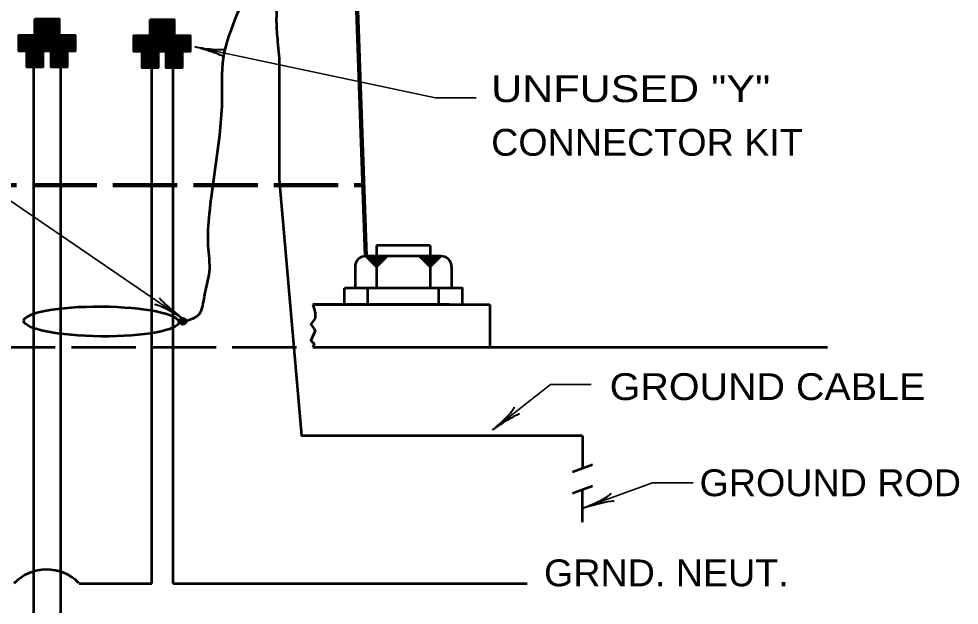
# Model space of a CAD drawing. Extents: x -153 to 527, y -247 to 194.
# Drawn here: x 102.3 to 190, y -178.9 to -124.2 of the extents above; entities that cross this region are included whole.
import ezdxf

# ---------------------------------------------------------------- set-up
doc = ezdxf.new("R2010")
doc.units = 0
doc.linetypes.add('LONG_DASHED', pattern=[7.5, 6, -1.5])
doc.layers.add('1', color=7, linetype='Continuous', lineweight=53)

msp = doc.modelspace()

# ---------------------------------------------------------------- linework, layer by layer
at = {"layer": '1', "lineweight": 90}
msp.add_line((134.641, -146.336), (131.815, -65.386), dxfattribs=at)
at = {"layer": '1'}
for p, q in [((103.79, -124.381), (106.04, -124.381)), ((114.525, -124.432), (116.775, -124.432)), ((103.79, -124.531), (106.04, -124.531)), ((103.79, -124.707), (106.04, -124.707)), ((103.79, -124.857), (106.04, -124.857)), ((103.79, -125.008), (106.04, -125.008)), ((103.79, -125.183), (106.04, -125.183)), ((103.79, -125.334), (106.04, -125.334)), ((114.525, -124.582), (116.775, -124.582)), ((114.525, -124.758), (116.775, -124.758)), ((114.525, -124.908), (116.775, -124.908)), ((114.525, -125.059), (116.775, -125.059)), ((114.525, -125.234), (116.775, -125.234)), ((102.29, -125.835), (103.79, -125.835)), ((102.29, -125.935), (103.79, -125.935)), ((102.29, -126.061), (103.79, -126.061)), ((102.29, -126.211), (103.79, -126.211)), ((103.79, -125.509), (106.04, -125.509)), ((103.79, -125.685), (106.04, -125.685)), ((103.79, -125.835), (106.04, -125.835)), ((103.79, -126.011), (106.04, -126.011)), ((103.79, -126.136), (106.04, -126.136)), ((103.79, -126.236), (106.04, -126.236)), ((106.04, -125.785), (107.54, -125.785)), ((106.04, -125.91), (107.54, -125.91)), ((106.04, -126.011), (107.54, -126.011)), ((106.04, -126.161), (107.54, -126.161)), ((113.025, -125.886), (114.525, -125.886)), ((113.025, -125.986), (114.525, -125.986)), ((113.025, -126.112), (114.525, -126.112)), ((114.525, -125.385), (116.775, -125.385)), ((114.525, -125.56), (116.775, -125.56)), ((114.525, -125.736), (116.775, -125.736)), ((114.525, -125.886), (116.775, -125.886)), ((114.525, -126.061), (116.775, -126.061)), ((114.525, -126.187), (116.775, -126.187)), ((116.775, -125.836), (118.275, -125.836)), ((116.775, -125.961), (118.275, -125.961)), ((116.775, -126.061), (118.275, -126.061)), ((116.775, -126.212), (118.275, -126.212)), ((102.29, -126.337), (103.79, -126.337)), ((102.29, -126.512), (103.79, -126.512)), ((102.29, -126.688), (103.79, -126.688)), ((102.29, -126.788), (103.79, -126.788)), ((102.29, -126.913), (103.79, -126.913)), ((102.29, -127.014), (103.79, -127.014)), ((103.79, -126.312), (106.04, -126.312)), ((103.79, -126.362), (106.04, -126.362)), ((103.79, -126.437), (106.04, -126.437)), ((103.79, -126.587), (106.04, -126.587)), ((103.79, -126.663), (106.04, -126.663)), ((103.79, -126.838), (106.04, -126.838)), ((103.79, -126.989), (106.04, -126.989)), ((103.79, -127.114), (106.04, -127.114)), ((106.04, -126.337), (107.54, -126.337)), ((106.04, -126.462), (107.54, -126.462)), ((106.04, -126.612), (107.54, -126.612)), ((106.04, -126.738), (107.54, -126.738)), ((106.04, -126.863), (107.54, -126.863)), ((106.04, -126.989), (107.54, -126.989)), ((113.025, -126.262), (114.525, -126.262)), ((113.025, -126.387), (114.525, -126.387)), ((113.025, -126.563), (114.525, -126.563)), ((113.025, -126.738), (114.525, -126.738)), ((113.025, -126.839), (114.525, -126.839)), ((113.025, -126.964), (114.525, -126.964)), ((113.025, -127.064), (114.525, -127.064)), ((114.525, -126.287), (116.775, -126.287)), ((114.525, -126.362), (116.775, -126.362)), ((114.525, -126.412), (116.775, -126.412)), ((114.525, -126.488), (116.775, -126.488)), ((114.525, -126.638), (116.775, -126.638)), ((114.525, -126.713), (116.775, -126.713)), ((114.525, -126.889), (116.775, -126.889)), ((114.525, -127.039), (116.775, -127.039)), ((116.775, -126.387), (118.275, -126.387)), ((116.775, -126.513), (118.275, -126.513)), ((116.775, -126.663), (118.275, -126.663)), ((116.775, -126.789), (118.275, -126.789)), ((116.775, -126.914), (118.275, -126.914)), ((116.775, -127.039), (118.275, -127.039)), ((102.29, -127.164), (103.79, -127.164)), ((104.54, -127.239), (103.04, -127.239)), ((104.54, -127.264), (103.04, -127.264)), ((104.54, -127.34), (103.04, -127.34)), ((104.54, -127.44), (103.04, -127.44)), ((104.54, -127.54), (103.04, -127.54)), ((104.54, -127.615), (103.04, -127.615)), ((104.54, -127.665), (103.04, -127.665)), ((104.54, -127.716), (103.04, -127.716)), ((104.54, -127.816), (103.04, -127.816)), ((104.54, -127.891), (103.04, -127.891)), ((104.54, -127.991), (103.04, -127.991)), ((106.79, -127.189), (105.29, -127.189)), ((106.79, -127.239), (105.29, -127.239)), ((106.79, -127.289), (105.29, -127.289)), ((106.79, -127.34), (105.29, -127.34)), ((106.79, -127.415), (105.29, -127.415)), ((106.79, -127.49), (105.29, -127.49)), ((106.79, -127.54), (105.29, -127.54)), ((106.79, -127.59), (105.29, -127.59)), ((106.79, -127.665), (105.29, -127.665)), ((106.79, -127.716), (105.29, -127.716)), ((106.79, -127.791), (105.29, -127.791)), ((106.79, -127.841), (105.29, -127.841)), ((106.79, -127.866), (105.29, -127.866)), ((106.79, -127.916), (105.29, -127.916)), ((106.79, -127.941), (105.29, -127.941)), ((106.79, -127.991), (105.29, -127.991)), ((106.04, -127.139), (107.54, -127.139)), ((113.025, -127.215), (114.525, -127.215)), ((115.275, -127.29), (113.775, -127.29)), ((115.275, -127.315), (113.775, -127.315)), ((115.275, -127.39), (113.775, -127.39)), ((115.275, -127.491), (113.775, -127.491)), ((115.275, -127.591), (113.775, -127.591)), ((115.275, -127.666), (113.775, -127.666)), ((115.275, -127.716), (113.775, -127.716)), ((115.275, -127.766), (113.775, -127.766)), ((115.275, -127.867), (113.775, -127.867)), ((115.275, -127.942), (113.775, -127.942)), ((114.525, -127.165), (116.775, -127.165)), ((117.525, -127.24), (116.025, -127.24)), ((117.525, -127.29), (116.025, -127.29)), ((117.525, -127.34), (116.025, -127.34)), ((117.525, -127.39), (116.025, -127.39)), ((117.525, -127.465), (116.025, -127.465)), ((117.525, -127.541), (116.025, -127.541)), ((117.525, -127.591), (116.025, -127.591)), ((117.525, -127.641), (116.025, -127.641)), ((117.525, -127.716), (116.025, -127.716)), ((117.525, -127.766), (116.025, -127.766)), ((117.525, -127.842), (116.025, -127.842)), ((117.525, -127.892), (116.025, -127.892)), ((117.525, -127.917), (116.025, -127.917)), ((117.525, -127.967), (116.025, -127.967)), ((117.525, -127.992), (116.025, -127.992)), ((116.775, -127.19), (118.275, -127.19)), ((104.54, -128.092), (103.04, -128.092)), ((104.54, -128.217), (103.04, -128.217)), ((104.54, -128.317), (103.04, -128.317)), ((104.54, -128.418), (103.04, -128.418)), ((104.54, -128.518), (103.04, -128.518)), ((104.54, -128.618), (103.04, -128.618)), ((103.692, -181.835), (103.692, -128.731)), ((106.79, -128.042), (105.29, -128.042)), ((106.79, -128.092), (105.29, -128.092)), ((106.79, -128.167), (105.29, -128.167)), ((106.79, -128.242), (105.29, -128.242)), ((106.79, -128.317), (105.29, -128.317)), ((106.79, -128.368), (105.29, -128.368)), ((106.79, -128.418), (105.29, -128.418)), ((106.79, -128.468), (105.29, -128.468)), ((106.79, -128.543), (105.29, -128.543)), ((106.79, -128.568), (105.29, -128.568)), ((106.192, -181.835), (106.192, -128.731)), ((115.275, -128.042), (113.775, -128.042)), ((115.275, -128.142), (113.775, -128.142)), ((115.275, -128.268), (113.775, -128.268)), ((115.275, -128.368), (113.775, -128.368)), ((115.275, -128.468), (113.775, -128.468)), ((115.275, -128.569), (113.775, -128.569)), ((115.275, -128.669), (113.775, -128.669)), ((114.692, -176.836), (114.692, -128.781)), ((117.525, -128.042), (116.025, -128.042)), ((117.525, -128.092), (116.025, -128.092)), ((117.525, -128.142), (116.025, -128.142)), ((117.525, -128.218), (116.025, -128.218)), ((117.525, -128.293), (116.025, -128.293)), ((117.525, -128.368), (116.025, -128.368)), ((117.525, -128.418), (116.025, -128.418)), ((117.525, -128.468), (116.025, -128.468)), ((117.525, -128.519), (116.025, -128.519)), ((117.525, -128.594), (116.025, -128.594)), ((117.525, -128.619), (116.025, -128.619)), ((116.692, -176.836), (116.692, -128.781)), ((135.641, -145.336), (135.641, -149.336)), ((140.641, -145.336), (135.641, -145.336)), ((140.641, -145.336), (140.641, -149.336)), ((135.635, -147.34), (134.635, -146.34)), ((141.641, -146.336), (134.641, -146.336)), ((135.641, -147.336), (134.641, -146.336)), ((135.649, -147.325), (134.664, -146.34)), ((135.662, -147.312), (134.686, -146.336)), ((135.662, -147.312), (134.689, -146.34)), ((135.674, -147.3), (134.714, -146.34)), ((135.687, -147.287), (134.739, -146.34)), ((135.693, -147.281), (134.752, -146.34)), ((135.696, -147.278), (134.754, -146.336)), ((135.707, -147.267), (134.776, -146.336)), ((135.709, -147.265), (134.783, -146.34)), ((135.71, -147.264), (134.786, -146.34)), ((135.721, -147.253), (134.808, -146.34)), ((135.688, -147.286), (134.816, -146.414)), ((135.726, -147.248), (134.817, -146.34)), ((135.704, -147.27), (134.832, -146.398)), ((135.709, -147.266), (134.836, -146.393)), ((135.71, -147.264), (134.838, -146.392)), ((135.71, -147.264), (134.838, -146.392)), ((135.737, -147.237), (134.84, -146.34)), ((135.718, -147.256), (134.846, -146.384)), ((135.723, -147.251), (134.85, -146.379)), ((135.745, -147.229), (134.855, -146.34)), ((135.727, -147.247), (134.855, -146.374)), ((135.746, -147.228), (134.858, -146.34)), ((135.748, -147.226), (134.875, -146.354)), ((135.757, -147.217), (134.885, -146.345)), ((135.76, -147.214), (134.888, -146.341)), ((135.762, -147.212), (134.89, -146.34)), ((135.77, -147.204), (134.902, -146.336)), ((135.773, -147.201), (134.911, -146.34)), ((135.782, -147.192), (134.93, -146.34)), ((135.793, -147.181), (134.949, -146.336)), ((135.795, -147.179), (134.955, -146.34)), ((135.798, -147.176), (134.962, -146.34)), ((135.803, -147.171), (134.971, -146.34)), ((135.81, -147.164), (134.983, -146.336)), ((135.812, -147.162), (134.99, -146.34)), ((135.823, -147.151), (135.008, -146.336)), ((135.825, -147.149), (135.015, -146.34)), ((135.829, -147.145), (135.021, -146.336)), ((135.828, -147.146), (135.021, -146.34)), ((135.839, -147.135), (135.043, -146.34)), ((135.848, -147.126), (135.059, -146.336)), ((135.854, -147.12), (135.071, -146.336)), ((135.859, -147.115), (135.081, -146.336)), ((135.864, -147.11), (135.09, -146.336)), ((135.862, -147.112), (135.09, -146.34)), ((135.868, -147.106), (135.096, -146.334)), ((135.867, -147.107), (135.1, -146.34)), ((135.878, -147.096), (135.118, -146.336)), ((135.878, -147.096), (135.118, -146.336)), ((135.876, -147.098), (135.118, -146.34)), ((135.884, -147.09), (135.131, -146.336)), ((135.891, -147.084), (135.143, -146.336)), ((135.9, -147.074), (135.162, -146.336)), ((135.901, -147.073), (135.165, -146.336)), ((135.906, -147.068), (135.174, -146.336)), ((135.912, -147.062), (135.19, -146.34)), ((135.917, -147.057), (135.196, -146.336)), ((135.925, -147.049), (135.216, -146.34)), ((135.93, -147.045), (135.221, -146.336)), ((135.936, -147.038), (135.237, -146.34)), ((135.925, -147.049), (135.275, -146.399)), ((135.963, -147.011), (135.291, -146.34)), ((135.942, -147.032), (135.292, -146.382)), ((135.964, -147.01), (135.314, -146.36)), ((135.974, -147.001), (135.324, -146.351)), ((135.978, -146.996), (135.328, -146.346)), ((135.985, -146.989), (135.335, -146.34)), ((135.992, -146.982), (135.347, -146.336)), ((135.994, -146.98), (135.353, -146.34)), ((136, -146.974), (135.366, -146.34)), ((136.008, -146.966), (135.378, -146.336)), ((136.008, -146.966), (135.378, -146.336)), ((136.016, -146.958), (135.394, -146.336)), ((136.024, -146.951), (135.41, -146.336)), ((136.025, -146.949), (135.413, -146.336)), ((136.027, -146.947), (135.419, -146.34)), ((136.03, -146.944), (135.422, -146.336)), ((136.03, -146.944), (135.422, -146.337)), ((136.036, -146.938), (135.435, -146.336)), ((136.035, -146.939), (135.435, -146.34)), ((136.041, -146.933), (135.444, -146.336)), ((136.05, -146.924), (135.463, -146.336)), ((136.051, -146.924), (135.467, -146.34)), ((136.058, -146.916), (135.479, -146.336)), ((136.066, -146.908), (135.498, -146.34)), ((136.093, -146.881), (135.551, -146.34)), ((136.102, -146.872), (135.566, -146.336)), ((136.112, -146.863), (135.585, -146.336)), ((136.113, -146.861), (135.588, -146.336)), ((135.635, -147.34), (136.635, -146.34)), ((135.641, -147.336), (136.641, -146.336)), ((136.138, -146.836), (135.642, -146.34)), ((136.138, -146.836), (135.642, -146.34)), ((136.149, -146.825), (135.661, -146.336)), ((136.151, -146.823), (135.672, -146.344)), ((136.155, -146.819), (135.676, -146.34)), ((136.159, -146.816), (135.679, -146.337)), ((136.162, -146.812), (135.685, -146.336)), ((136.165, -146.809), (135.692, -146.336)), ((136.171, -146.803), (135.704, -146.336)), ((136.179, -146.795), (135.72, -146.336)), ((136.185, -146.789), (135.736, -146.34)), ((136.191, -146.783), (135.745, -146.336)), ((136.198, -146.776), (135.761, -146.34)), ((136.202, -146.772), (135.767, -146.336)), ((136.214, -146.761), (135.793, -146.34)), ((136.224, -146.75), (135.814, -146.34)), ((136.227, -146.747), (135.817, -146.336)), ((136.235, -146.739), (135.833, -146.336)), ((136.251, -146.723), (135.868, -146.34)), ((136.27, -146.704), (135.902, -146.336)), ((136.268, -146.706), (135.902, -146.34)), ((136.273, -146.701), (135.911, -146.34)), ((136.276, -146.698), (135.915, -146.336)), ((136.282, -146.692), (135.927, -146.336)), ((136.285, -146.689), (135.933, -146.336)), ((136.293, -146.681), (135.949, -146.336)), ((136.308, -146.667), (135.977, -146.336)), ((136.315, -146.659), (135.993, -146.336)), ((136.326, -146.648), (136.015, -146.336)), ((136.345, -146.629), (136.053, -146.336)), ((136.351, -146.623), (136.065, -146.336)), ((136.356, -146.618), (136.077, -146.34)), ((136.383, -146.591), (136.131, -146.34)), ((136.394, -146.58), (136.153, -146.34)), ((136.414, -146.56), (136.194, -146.34)), ((136.427, -146.547), (136.219, -146.34)), ((136.434, -146.54), (136.23, -146.336)), ((136.439, -146.535), (136.24, -146.336)), ((136.442, -146.532), (136.247, -146.336)), ((136.477, -146.497), (136.319, -146.34)), ((136.483, -146.491), (136.328, -146.336)), ((136.503, -146.471), (136.369, -146.336)), ((136.48, -146.495), (136.397, -146.412)), ((136.514, -146.46), (136.431, -146.378)), ((136.519, -146.456), (136.436, -146.373)), ((136.54, -146.435), (136.441, -146.336)), ((136.529, -146.446), (136.446, -146.363)), ((136.532, -146.442), (136.449, -146.36)), ((136.552, -146.422), (136.469, -146.34)), ((136.555, -146.419), (136.473, -146.337)), ((136.56, -146.414), (136.482, -146.336)), ((136.569, -146.405), (136.501, -146.336)), ((136.623, -146.351), (136.607, -146.336)), ((140.641, -147.336), (139.641, -146.336)), ((140.656, -147.322), (139.671, -146.336)), ((140.669, -147.309), (139.696, -146.336)), ((140.669, -147.309), (139.696, -146.336)), ((140.681, -147.297), (139.721, -146.336)), ((140.694, -147.284), (139.746, -146.336)), ((140.7, -147.278), (139.758, -146.336)), ((140.716, -147.262), (139.79, -146.336)), ((140.717, -147.261), (139.793, -146.336)), ((140.728, -147.25), (139.815, -146.336)), ((140.733, -147.245), (139.824, -146.336)), ((140.744, -147.234), (139.846, -146.336)), ((140.744, -147.234), (139.847, -146.336)), ((140.752, -147.226), (139.862, -146.336)), ((140.753, -147.225), (139.865, -146.336)), ((140.763, -147.215), (139.884, -146.336)), ((140.766, -147.212), (139.89, -146.336)), ((140.769, -147.209), (139.897, -146.336)), ((140.789, -147.189), (139.937, -146.336)), ((140.802, -147.176), (139.962, -146.336)), ((140.81, -147.168), (139.978, -146.336)), ((140.819, -147.159), (139.997, -146.336)), ((140.832, -147.146), (140.022, -146.336)), ((140.846, -147.132), (140.05, -146.336)), ((140.853, -147.124), (140.065, -146.336)), ((140.86, -147.118), (140.078, -146.336)), ((140.869, -147.108), (140.097, -146.336)), ((140.874, -147.104), (140.106, -146.336)), ((140.883, -147.094), (140.125, -146.336)), ((140.89, -147.088), (140.138, -146.336)), ((140.9, -147.077), (140.16, -146.336)), ((140.919, -147.058), (140.197, -146.336)), ((140.929, -147.049), (140.216, -146.336)), ((140.932, -147.046), (140.222, -146.336)), ((140.932, -147.046), (140.223, -146.336)), ((140.943, -147.035), (140.244, -146.336)), ((140.951, -147.027), (140.26, -146.336)), ((140.965, -147.013), (140.288, -146.336)), ((140.97, -147.008), (140.298, -146.336)), ((140.982, -146.996), (140.323, -146.336)), ((140.992, -146.986), (140.342, -146.336)), ((141.001, -146.977), (140.36, -146.336)), ((141.007, -146.971), (140.373, -146.336)), ((141.009, -146.969), (140.376, -146.336)), ((141.034, -146.944), (140.426, -146.336)), ((141.042, -146.936), (140.442, -146.336)), ((141.048, -146.93), (140.454, -146.336)), ((141.054, -146.924), (140.467, -146.336)), ((141.054, -146.924), (140.467, -146.336)), ((141.057, -146.92), (140.473, -146.336)), ((141.057, -146.921), (140.473, -146.336)), ((141.062, -146.916), (140.482, -146.336)), ((141.073, -146.905), (140.505, -146.336)), ((141.1, -146.878), (140.558, -146.336)), ((141.111, -146.867), (140.58, -146.336)), ((141.118, -146.859), (140.595, -146.336)), ((140.641, -147.336), (141.641, -146.336)), ((141.145, -146.833), (140.649, -146.336)), ((141.145, -146.833), (140.649, -146.336)), ((141.15, -146.828), (140.658, -146.336)), ((141.156, -146.822), (140.671, -146.336)), ((141.159, -146.819), (140.677, -146.336)), ((141.162, -146.815), (140.683, -146.336)), ((141.165, -146.812), (140.689, -146.336)), ((141.192, -146.786), (140.743, -146.336)), ((141.205, -146.773), (140.768, -146.336)), ((141.211, -146.767), (140.78, -146.336)), ((141.214, -146.764), (140.787, -146.336)), ((141.22, -146.757), (140.799, -146.336)), ((141.225, -146.753), (140.809, -146.336)), ((141.231, -146.747), (140.821, -146.336)), ((141.236, -146.742), (140.831, -146.336)), ((141.258, -146.72), (140.875, -146.336)), ((141.275, -146.703), (140.909, -146.336)), ((141.28, -146.698), (140.918, -146.336)), ((141.285, -146.693), (140.928, -146.336)), ((141.314, -146.663), (140.987, -146.336)), ((141.322, -146.656), (141.003, -146.336)), ((141.333, -146.645), (141.025, -146.336)), ((141.335, -146.643), (141.028, -146.336)), ((141.352, -146.626), (141.062, -146.336)), ((141.363, -146.615), (141.084, -146.336)), ((141.39, -146.588), (141.138, -146.336)), ((141.421, -146.557), (141.201, -146.336)), ((141.426, -146.552), (141.21, -146.336)), ((141.434, -146.544), (141.226, -146.336)), ((141.438, -146.54), (141.235, -146.336)), ((141.46, -146.518), (141.279, -146.336)), ((141.484, -146.494), (141.326, -146.336)), ((141.486, -146.492), (141.404, -146.409)), ((141.521, -146.457), (141.438, -146.375)), ((141.525, -146.452), (141.443, -146.37)), ((141.529, -146.449), (141.446, -146.367)), ((141.546, -146.432), (141.463, -146.35)), ((141.559, -146.419), (141.476, -146.336)), ((141.601, -146.377), (141.56, -146.337)), ((141.608, -146.369), (141.575, -146.336)), ((141.615, -146.363), (141.589, -146.337)), ((141.621, -146.357), (141.604, -146.34)), ((135.873, -147.101), (135.223, -146.451)), ((135.9, -147.074), (135.25, -146.424)), ((135.908, -147.066), (135.258, -146.417)), ((135.762, -147.213), (135.679, -147.13)), ((135.798, -147.177), (135.716, -147.094)), ((136.044, -146.931), (135.962, -146.848)), ((136.268, -146.706), (135.979, -146.416)), ((136.108, -146.866), (136.026, -146.784)), ((136.162, -146.813), (136.079, -146.731)), ((136.179, -146.796), (136.096, -146.713)), ((136.221, -146.753), (136.138, -146.671)), ((136.284, -146.691), (136.201, -146.608)), ((136.357, -146.617), (136.275, -146.535)), ((136.469, -146.506), (136.386, -146.423)), ((140.739, -147.239), (140.657, -147.157)), ((140.805, -147.174), (140.722, -147.091)), ((140.875, -147.103), (140.793, -147.021)), ((140.965, -147.014), (140.882, -146.931)), ((141.051, -146.927), (140.968, -146.845)), ((141.063, -146.915), (140.981, -146.832)), ((141.084, -146.894), (141.001, -146.812)), ((141.087, -146.891), (141.005, -146.809)), ((141.115, -146.863), (141.033, -146.781)), ((141.118, -146.86), (141.036, -146.777)), ((141.145, -146.833), (141.062, -146.751)), ((141.153, -146.826), (141.07, -146.743)), ((141.168, -146.81), (141.086, -146.727)), ((141.186, -146.793), (141.103, -146.71)), ((141.228, -146.75), (141.145, -146.668)), ((141.291, -146.688), (141.208, -146.605)), ((141.342, -146.636), (141.26, -146.553)), ((141.392, -146.586), (141.31, -146.503)), ((141.424, -146.554), (141.341, -146.472)), ((141.461, -146.517), (141.379, -146.434)), ((141.475, -146.502), (141.393, -146.42)), ((133.641, -147.336), (133.641, -149.336)), ((142.641, -147.336), (142.641, -149.336)), ((132.641, -150.836), (132.641, -149.336)), ((134.839, -150.836), (134.839, -149.336)), ((141.451, -150.836), (141.451, -149.336)), ((129.692, -150.836), (146.192, -150.836)), ((142.4, -150.836), (129.692, -150.836)), ((146.192, -150.836), (146.192, -154.836)), ((129.692, -154.836), (177.692, -154.836)), ((154.841, -163.092), (154.841, -166.092)), ((153.902, -166.434), (155.781, -165.75)), ((153.902, -168.434), (155.781, -167.75)), ((154.826, -168.117), (154.826, -171.117)), ((107.915, -176.836), (114.692, -176.836)), ((116.692, -176.836), (149.692, -176.836))]:
    msp.add_line(p, q, dxfattribs=at)
at = {"layer": '1', "lineweight": 35}
for p, q in [((118.714, -126.824), (141.129, -131.588)), ((87.001, -131.25), (117.556, -152.159)), ((144.928, -131.588), (141.129, -131.588)), ((151.852, -158.315), (146.47, -162.52)), ((155.65, -158.315), (151.852, -158.315)), ((161.361, -167.474), (154.942, -169.81)), ((165.159, -167.474), (161.361, -167.474))]:
    msp.add_line(p, q, dxfattribs=at)
at = {"layer": '1', "linetype": 'LONG_DASHED', "lineweight": 90}
msp.add_line((88.564, -139.723), (134.41, -139.723), dxfattribs=at)
at = {"layer": '1', "linetype": 'LONG_DASHED'}
msp.add_line((92.192, -154.836), (129.692, -154.836), dxfattribs=at)
at = {"layer": '1'}
for points in [[(103.79, -124.231), (106.04, -124.231), (106.04, -125.731), (107.54, -125.731), (107.54, -127.231), (106.79, -127.231), (106.79, -128.731), (105.29, -128.731), (105.29, -127.231), (104.54, -127.231), (104.54, -128.731), (103.04, -128.731), (103.04, -127.231), (102.29, -127.231), (102.29, -125.731), (103.79, -125.731)], [(114.525, -124.281), (116.775, -124.281), (116.775, -125.781), (118.275, -125.781), (118.275, -127.281), (117.525, -127.281), (117.525, -128.781), (116.025, -128.781), (116.025, -127.281), (115.275, -127.281), (115.275, -128.781), (113.775, -128.781), (113.775, -127.281), (113.025, -127.281), (113.025, -125.781), (114.525, -125.781)]]:
    msp.add_lwpolyline(points, close=True, dxfattribs=at)
for points in [[(154.841, -163.092), (128.687, -163.092), (126.595, -139.184), (126.595, -130.184)], [(143.641, -150.836), (143.641, -149.336), (132.641, -149.336)], [(129.692, -150.836), (129.91, -151.606), (129.91, -152.108), (129.509, -152.71), (129.81, -153.111), (129.91, -153.312), (129.509, -154.215), (129.81, -154.516), (129.692, -154.836)]]:
    msp.add_lwpolyline(points, dxfattribs=at)
for centre, radius in [((117.578, -152.413), 0.3), ((117.566, -152.403), 0.277), ((117.569, -152.41), 0.248), ((117.557, -152.406), 0.217), ((117.569, -152.419), 0.211), ((117.422, -152.416), 0.0536), ((117.575, -152.391), 0.203), ((117.566, -152.391), 0.174), ((117.557, -152.384), 0.143), ((117.566, -152.381), 0.117), ((117.541, -152.413), 0.0836), ((117.494, -152.538), 0.0309), ((117.55, -152.388), 0.0745), ((117.557, -152.341), 0.0659), ((117.575, -152.375), 0.0813), ((117.553, -152.29), 0.0565), ((117.585, -152.322), 0.0715), ((117.547, -152.378), 0.0201), ((117.604, -152.547), 0.069), ((117.588, -152.384), 0.0399), ((117.613, -152.563), 0.0129), ((117.61, -152.541), 0.007), ((117.632, -152.522), 0.0239), ((117.663, -152.413), 0.0157), ((117.685, -152.331), 0.0313), ((117.741, -152.444), 0.0401), ((117.763, -152.372), 0.0133)]:
    msp.add_circle(centre, radius, dxfattribs=at)
for centre, radius, start, end in [((134.641, -147.336), 1, 90, 180), ((141.641, -147.336), 1, 0, 90), ((104.886, -179.736), 4.193, 44.31179, 136.66815), ((104.886, -179.736), 4.193, 43.26875, 43.74948)]:
    msp.add_arc(centre, radius, start, end, dxfattribs=at)
at = {"layer": '1', "lineweight": 40}
for centre, major_axis, ratio, start_param, end_param in [((119.766, -127.264), (1.682, -0.537), 0.07063, 6.282307, 8.559703), ((119.839, -126.781), (-1.779, 0.218), 0.122415, 0.896353, 3.141593), ((116.751, -151.351), (-1.35, 1.137), 0.07063, 6.282307, 8.559703), ((116.5, -151.771), (1.562, -0.88), 0.122415, 0.896353, 3.141593), ((147.16, -161.631), (-1.311, -1.222), 0.122415, 0.896353, 3.141593), ((147.483, -161.997), (1.492, 0.943), 0.07063, 6.282307, 8.559703), ((155.873, -169.177), (-1.625, -0.757), 0.122415, 0.896353, 3.141593), ((156.068, -169.626), (1.711, 0.436), 0.07063, 6.282307, 8.559703)]:
    msp.add_ellipse(centre, major_axis=major_axis, ratio=ratio, start_param=start_param, end_param=end_param, dxfattribs=at)
at = {"layer": '1'}
msp.add_ellipse((109.981, -152.423), major_axis=(-7.22, 0.055), ratio=0.192922, dxfattribs=at)
for points in [[(117.71, -152.418), (119.126, -151.71), (119.598, -150.057), (120.07, -147.815), (119.953, -145.336), (120.07, -142.385), (120.543, -138.726), (121.015, -135.067), (121.251, -131.998), (121.369, -127.867), (122.313, -124.68), (123.966, -120.903), (125.618, -117.835), (126.68, -115.238), (128.215, -110.517), (129.631, -105.795)], [(126.595, -130.184), (126.562, -127.602), (126.444, -126.363), (126.326, -124.474), (126.503, -122.527), (126.916, -121.169), (127.329, -119.163), (127.979, -116.979), (128.44, -115.843)]]:
    msp.add_spline(points, degree=3, dxfattribs=at)

# ---------------------------------------------------------------- texts
for s, width, p in [('UNFUSED "Y"', 1.2, (146.325, -131.981)), ('CONNECTOR KIT ', 1.05, (146.325, -136.981)), ('GROUND CABLE', 1.1, (157.378, -159.749)), ('GROUND ROD', 1.05, (165.753, -168.708)), ('GRND. NEUT.', 1.05, (151.252, -177.105))]:
    msp.add_text(s, height=2.5, dxfattribs=dict(at, width=width)).set_placement(p)

doc.saveas('drawing.dxf')
